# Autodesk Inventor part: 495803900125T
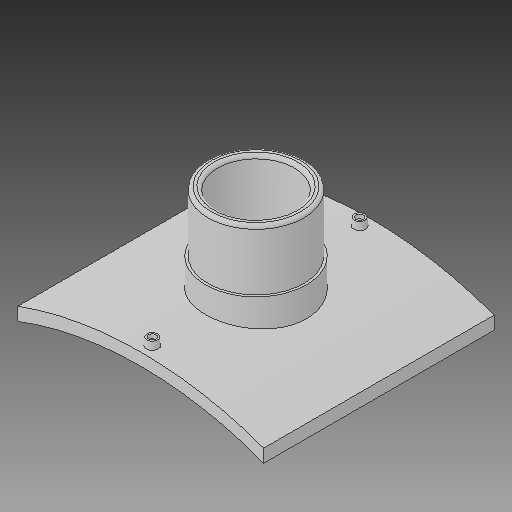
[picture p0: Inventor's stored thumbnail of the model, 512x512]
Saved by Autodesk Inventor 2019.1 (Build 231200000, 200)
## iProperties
Created: 2017-10
Part Number: 495803900125T
Material: Generic
Description: PLASSON BRANCH SADDLE 900x125
Document SubType Name: Modeling
Designer: KIM
Mass: 2754.05 g
Surface Area: 3037.44 cm^2
Volume: 2754.05 cm^3
Density: 1 g/cm^3
Appearance: Default
Author: KIM
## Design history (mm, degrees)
derived "495803.ipt"
feature "Solid1::495803.ipt"
tag "TaggingFeature1"
body "Solid1"
other parameters: "d1" = 16, "d4" = 0, "d12" = 475.6, "d13" = 14, "d14" = 135, "d16" = 5 deg, "d18" = 4, "d19" = 14, "d20" = 0, "d21" = 3, "d22" = 0, "d23" = 578, "d24" = 131.25, "d25" = 16, "d28" = 0, "d29" = 9.6, "d31" = 0, "d32" = 56, "d33" = 0, "d34" = 9, "d36" = 125, "d37" = 78.4, "d38" = 0, "d39" = 4.5, "d_1" = 125, "H_" = 112, "x_" = 16, "D_" = 16
